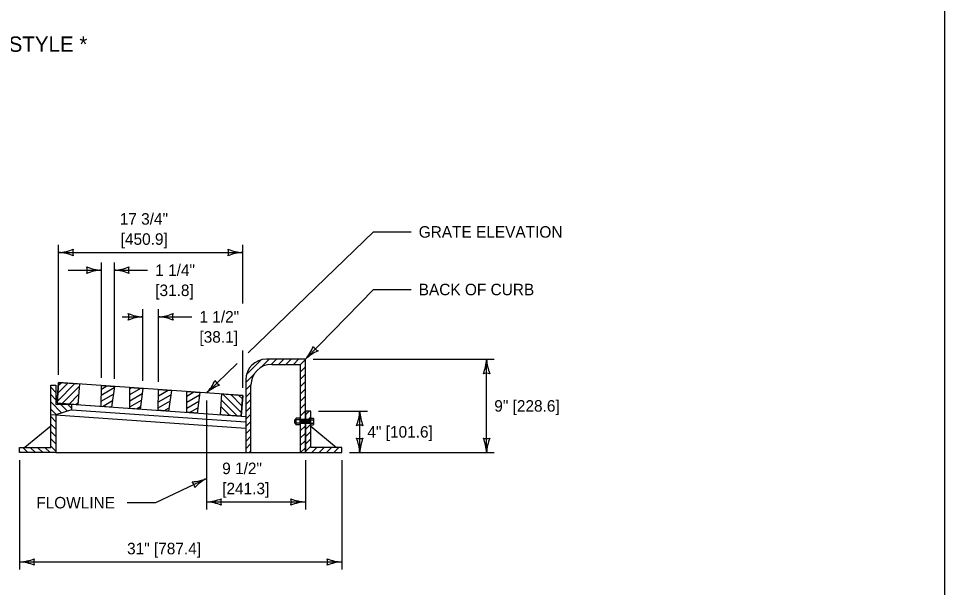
# Model space of a CAD drawing. Extents: x 49991.4 to 50057, y 49987.6 to 50011.4.
# Drawn here: x 50011.925 to 50016.75, y 49993.242 to 49996.209 of the extents above; entities that cross this region are included whole.
import ezdxf

# ---------------------------------------------------------------- set-up
doc = ezdxf.new("R2010")
doc.units = 0
for name, color, linetype in [('Level 1', 7, 'Continuous'), ('Level 2', 7, 'Continuous'), ('Level 3', 7, 'Continuous')]:
    doc.layers.add(name, color=color, linetype=linetype)

msp = doc.modelspace()

# ---------------------------------------------------------------- linework, layer by layer
at = {"layer": 'Level 1'}
for p, q in [((50013.113, 49994.3523), (50013.1892, 49994.4285)), ((50013.1885, 49994.3896), (50013.2313, 49994.4323)), ((50013.2425, 49994.4052), (50013.2696, 49994.4323)), ((50013.2808, 49994.4052), (50013.3079, 49994.4323)), ((50013.3191, 49994.4052), (50013.3462, 49994.4323)), ((50013.3574, 49994.4052), (50013.3845, 49994.4323)), ((50013.3936, 49994.4031), (50013.4206, 49994.4302)), ((50013.3936, 49994.3648), (50013.4206, 49994.3919)), ((50012.1344, 49994.3104), (50012.1269, 49994.2024)), ((50013.0935, 49994.2434), (50012.1344, 49994.3104)), ((50013.1092, 49994.3102), (50013.1519, 49994.353)), ((50013.3936, 49994.3265), (50013.4206, 49994.3536)), ((50013.3936, 49994.2882), (50013.4206, 49994.3153)), ((50012.0936, 49994.2857), (50012.1206, 49994.2586)), ((50012.1277, 49994.2138), (50012.2184, 49994.3046)), ((50012.1305, 49994.255), (50012.1826, 49994.3071)), ((50012.1334, 49994.2961), (50012.1468, 49994.3096)), ((50012.1527, 49994.2005), (50012.2415, 49994.2894)), ((50012.3569, 49994.2453), (50012.424, 49994.2841)), ((50012.3572, 49994.2767), (50012.3852, 49994.2929)), ((50012.5056, 49994.2473), (50012.5631, 49994.2805)), ((50012.5059, 49994.2787), (50012.5148, 49994.2838)), ((50012.6543, 49994.2406), (50012.706, 49994.2705)), ((50012.6545, 49994.272), (50012.6577, 49994.2738)), ((50013.1092, 49994.2719), (50013.1363, 49994.299)), ((50013.3936, 49994.2499), (50013.4206, 49994.277)), ((50012.0936, 49994.2474), (50012.1206, 49994.2203)), ((50012.1885, 49994.198), (50012.2387, 49994.2482)), ((50012.3567, 49994.2139), (50012.4195, 49994.2502)), ((50012.3624, 49994.1859), (50012.415, 49994.2163)), ((50012.5052, 49994.1844), (50012.5654, 49994.2192)), ((50012.5054, 49994.2158), (50012.5699, 49994.2531)), ((50012.654, 49994.2092), (50012.719, 49994.2467)), ((50012.8027, 49994.2086), (50012.869, 49994.2469)), ((50012.8029, 49994.24), (50012.8395, 49994.2611)), ((50012.9832, 49994.2189), (50013.0654, 49994.1367)), ((50012.9898, 49994.2506), (50013.0872, 49994.1532)), ((50013.031, 49994.2477), (50013.0897, 49994.189)), ((50013.0722, 49994.2449), (50013.0922, 49994.2248)), ((50013.086, 49994.135), (50013.0935, 49994.2434)), ((50013.1092, 49994.2336), (50013.1363, 49994.2607)), ((50013.1092, 49994.1953), (50013.1363, 49994.2224)), ((50013.3936, 49994.2116), (50013.4206, 49994.2387)), ((50012.0936, 49994.2091), (50012.1513, 49994.1514)), ((50012.0936, 49994.1708), (50012.1226, 49994.1418)), ((50012.1269, 49994.2024), (50013.086, 49994.1353)), ((50012.1452, 49994.1958), (50012.18, 49994.161)), ((50012.1828, 49994.1965), (50012.2019, 49994.1774)), ((50012.2019, 49994.1968), (50012.2019, 49994.1968)), ((50012.2019, 49994.1968), (50013.1092, 49994.1333)), ((50012.2019, 49994.1683), (50013.1092, 49994.1048)), ((50012.2243, 49994.1955), (50012.2358, 49994.207)), ((50012.5403, 49994.1735), (50012.5609, 49994.1853)), ((50012.6538, 49994.1778), (50012.7145, 49994.2128)), ((50012.6832, 49994.1635), (50012.71, 49994.179)), ((50012.8025, 49994.1772), (50012.8645, 49994.213)), ((50012.8167, 49994.1541), (50012.86, 49994.1792)), ((50012.9807, 49994.1831), (50013.0243, 49994.1396)), ((50013.1092, 49994.157), (50013.1363, 49994.1841)), ((50013.3936, 49994.1733), (50013.4206, 49994.2004)), ((50012.0936, 49994.1431), (50013.1092, 49994.072)), ((50012.0936, 49994.1325), (50012.1206, 49994.1054)), ((50012.2679, 49994.1635), (50012.2679, 49994.1635)), ((50012.9782, 49994.1473), (50012.9831, 49994.1424)), ((50013.1092, 49994.1187), (50013.1363, 49994.1458)), ((50013.3628, 49994.1141), (50013.3661, 49994.1175)), ((50013.3661, 49994.1175), (50013.3661, 49994.0972)), ((50013.3695, 49994.1175), (50013.3661, 49994.1175)), ((50013.3695, 49994.0941), (50013.3695, 49994.1205)), ((50013.3695, 49994.1175), (50013.3695, 49994.0972)), ((50013.3927, 49994.1249), (50013.3718, 49994.1249)), ((50013.3927, 49994.0897), (50013.3927, 49994.1249)), ((50013.3936, 49994.1225), (50013.3927, 49994.1225)), ((50013.3936, 49994.135), (50013.4206, 49994.1621)), ((50013.3936, 49994.0967), (50013.4206, 49994.1238)), ((50013.3936, 49994.0921), (50013.3936, 49994.1225)), ((50013.4477, 49994.1175), (50013.3936, 49994.1175)), ((50013.3966, 49994.1175), (50013.3966, 49994.0972)), ((50013.4, 49994.1175), (50013.4, 49994.0972)), ((50013.4033, 49994.1175), (50013.4033, 49994.0972)), ((50013.4067, 49994.1175), (50013.4067, 49994.0972)), ((50013.4101, 49994.1175), (50013.4101, 49994.0972)), ((50013.4135, 49994.1175), (50013.4135, 49994.0972)), ((50013.4169, 49994.1175), (50013.4169, 49994.0972)), ((50013.4203, 49994.1175), (50013.4203, 49994.0972)), ((50013.4206, 49994.1422), (50013.4399, 49994.1615)), ((50013.4206, 49994.1039), (50013.4477, 49994.131)), ((50013.4237, 49994.1175), (50013.4237, 49994.0972)), ((50013.427, 49994.1175), (50013.427, 49994.0972)), ((50013.4304, 49994.1175), (50013.4304, 49994.0972)), ((50013.4338, 49994.1175), (50013.4338, 49994.0972)), ((50013.4372, 49994.1175), (50013.4372, 49994.0972)), ((50013.4406, 49994.1175), (50013.4406, 49994.0972)), ((50013.444, 49994.1175), (50013.444, 49994.0972)), ((50013.4477, 49994.0921), (50013.4477, 49994.1225)), ((50013.4477, 49994.1225), (50013.4486, 49994.1225)), ((50013.4486, 49994.1249), (50013.4613, 49994.1249)), ((50013.4486, 49994.0897), (50013.4486, 49994.1249)), ((50013.4637, 49994.0941), (50013.4637, 49994.1205)), ((50012.0936, 49994.083), (50011.9581, 49993.9719)), ((50012.0936, 49994.0942), (50012.1206, 49994.0671)), ((50013.1092, 49994.0804), (50013.1363, 49994.1075)), ((50013.1092, 49994.0421), (50013.1363, 49994.0692)), ((50013.3627, 49994.1141), (50013.3627, 49994.1005)), ((50013.3628, 49994.1005), (50013.3661, 49994.0972)), ((50013.3644, 49994.1141), (50013.3644, 49994.1005)), ((50013.3695, 49994.0972), (50013.3661, 49994.0972)), ((50013.3678, 49994.1141), (50013.3678, 49994.1005)), ((50013.3927, 49994.1161), (50013.3718, 49994.1161)), ((50013.3927, 49994.0985), (50013.3718, 49994.0985)), ((50013.3927, 49994.0897), (50013.3718, 49994.0897)), ((50013.3936, 49994.0921), (50013.3927, 49994.0921)), ((50013.4477, 49994.0972), (50013.3936, 49994.0972)), ((50013.3936, 49994.0584), (50013.4206, 49994.0855)), ((50013.3949, 49994.1141), (50013.3949, 49994.1005)), ((50013.3983, 49994.1141), (50013.3983, 49994.1005)), ((50013.4017, 49994.1141), (50013.4017, 49994.1005)), ((50013.405, 49994.1141), (50013.405, 49994.1005)), ((50013.4084, 49994.1141), (50013.4084, 49994.1005)), ((50013.4118, 49994.1141), (50013.4118, 49994.1005)), ((50013.4152, 49994.1141), (50013.4152, 49994.1005)), ((50013.4186, 49994.1141), (50013.4186, 49994.1005)), ((50013.4206, 49994.0656), (50013.4477, 49994.0927)), ((50013.422, 49994.1141), (50013.422, 49994.1005)), ((50013.4254, 49994.1141), (50013.4254, 49994.1005)), ((50013.4287, 49994.1141), (50013.4287, 49994.1005)), ((50013.4321, 49994.1141), (50013.4321, 49994.1005)), ((50013.4355, 49994.1141), (50013.4355, 49994.1005)), ((50013.4389, 49994.1141), (50013.4389, 49994.1005)), ((50013.4423, 49994.1141), (50013.4423, 49994.1005)), ((50013.4457, 49994.1141), (50013.4457, 49994.1005)), ((50013.4477, 49994.0921), (50013.4486, 49994.0921)), ((50013.4477, 49994.083), (50013.4477, 49994.083)), ((50013.4477, 49994.083), (50013.5831, 49993.9719)), ((50013.4486, 49994.1161), (50013.4613, 49994.1161)), ((50013.4486, 49994.0985), (50013.4613, 49994.0985)), ((50013.4486, 49994.0897), (50013.4613, 49994.0897)), ((50012.0936, 49994.0559), (50012.1206, 49994.0288)), ((50013.1092, 49994.0038), (50013.1363, 49994.0309)), ((50013.3936, 49994.0201), (50013.4206, 49994.0472)), ((50013.4206, 49994.0273), (50013.4477, 49994.0544)), ((50012.0936, 49994.0176), (50012.1206, 49993.9905)), ((50012.0936, 49993.9793), (50012.1206, 49993.9522)), ((50013.1092, 49993.9655), (50013.1363, 49993.9926)), ((50013.3936, 49993.9818), (50013.4206, 49994.0089)), ((50013.4206, 49993.989), (50013.4477, 49994.0161)), ((50013.4206, 49993.9507), (50013.4477, 49993.9778)), ((50011.9311, 49993.9503), (50011.9365, 49993.9448)), ((50011.9311, 49993.9503), (50011.9365, 49993.9448)), ((50011.9311, 49993.9448), (50011.9311, 49993.9448)), ((50011.9477, 49993.9719), (50011.9748, 49993.9448)), ((50011.9581, 49993.9719), (50011.9581, 49993.9719)), ((50011.986, 49993.9719), (50012.0131, 49993.9448)), ((50012.0244, 49993.9719), (50012.0514, 49993.9448)), ((50012.0627, 49993.9719), (50012.0897, 49993.9448)), ((50012.1206, 49993.9448), (50013.4206, 49993.9448)), ((50013.1268, 49993.9448), (50013.1363, 49993.9543)), ((50013.3949, 49993.9448), (50013.4206, 49993.9706)), ((50013.4531, 49993.9448), (50013.4801, 49993.9719)), ((50013.4914, 49993.9448), (50013.5184, 49993.9719)), ((50013.5297, 49993.9448), (50013.5567, 49993.9719)), ((50013.568, 49993.9448), (50013.595, 49993.9719)), ((50013.5831, 49993.9719), (50013.5831, 49993.9719)), ((50013.6063, 49993.9448), (50013.6102, 49993.9488))]:
    msp.add_line(p, q, dxfattribs=at)
for points in [[(49999.3835, 49998.9992), (50016.7501, 49998.9992), (50016.7501, 49987.7988), (49999.3835, 49987.7988)], [(50012.1344, 49994.3104), (50012.2425, 49994.3029), (50012.2349, 49994.1947), (50012.1269, 49994.2023)], [(50012.1206, 49994.1412), (50012.1206, 49993.9448), (50011.9311, 49993.9448), (50011.9311, 49993.9719), (50012.0936, 49993.9719), (50012.0936, 49994.2969), (50012.1206, 49994.2969), (50012.1206, 49994.1953), (50012.2019, 49994.1968), (50012.2019, 49994.1683)], [(50012.3565, 49994.1863), (50012.3573, 49994.2948), (50012.4249, 49994.2901), (50012.4105, 49994.1825)], [(50012.5051, 49994.1759), (50012.5059, 49994.2845), (50012.5734, 49994.2797), (50012.5591, 49994.1721)], [(50012.5051, 49994.1759), (50012.5059, 49994.2845), (50012.5734, 49994.2797), (50012.5591, 49994.1721)], [(50012.6537, 49994.1655), (50012.6545, 49994.2741), (50012.722, 49994.2693), (50012.7077, 49994.1617)], [(50012.8023, 49994.1551), (50012.8031, 49994.2637), (50012.8706, 49994.259), (50012.8563, 49994.1514)], [(50012.8023, 49994.1551), (50012.8031, 49994.2637), (50012.8706, 49994.259), (50012.8563, 49994.1514)], [(50012.9855, 49994.2509), (50013.0935, 49994.2434), (50013.086, 49994.1352), (50012.9779, 49994.1428)], [(50013.4477, 49993.9719), (50013.4477, 49994.1615), (50013.4206, 49994.1615), (50013.4206, 49993.9448), (50013.6102, 49993.9448), (50013.6102, 49993.9719)]]:
    msp.add_lwpolyline(points, close=True, dxfattribs=at)
for points in [[(50013.4206, 49993.9448), (50013.4206, 49994.4323), (50013.2175, 49994.4323)], [(50013.2446, 49994.4052), (50013.3936, 49994.4052), (50013.3936, 49993.9448), (50013.4206, 49993.9448)], [(50013.1092, 49994.324), (50013.1092, 49993.9448), (50013.1363, 49993.9448), (50013.1363, 49994.2969)]]:
    msp.add_lwpolyline(points, dxfattribs=at)
for centre, radius, start, end in [((50013.2175, 49994.324), 0.1083, 90, 180), ((50013.2446, 49994.2969), 0.1083, 90, 180), ((50013.3748, 49994.1205), 0.00528, 123.6844, 236.3156), ((50013.4584, 49994.1205), 0.00528, 303.6844, 56.3156), ((50013.3871, 49994.1073), 0.0176, 150.0207, 209.9793), ((50013.3748, 49994.0941), 0.00528, 123.6376, 236.3624), ((50013.4461, 49994.1073), 0.0176, 330.0207, 29.9793), ((50013.4584, 49994.0941), 0.00528, 303.6376, 56.3624)]:
    msp.add_arc(centre, radius, start, end, dxfattribs=at)
at = {"layer": 'Level 3'}
for p, q in [((50013.1223, 49994.4652), (50013.7756, 49995.0958)), ((50013.7756, 49995.0958), (50013.9706, 49995.0958)), ((50012.1344, 49994.3504), (50012.1344, 49995.0286)), ((50012.1344, 49994.9886), (50013.0935, 49994.9886)), ((50013.0935, 49994.7232), (50013.0935, 49995.0286)), ((50012.1839, 49994.8963), (50012.3573, 49994.8963)), ((50012.3573, 49994.3348), (50012.3573, 49994.9363)), ((50012.4249, 49994.3301), (50012.4249, 49994.9363)), ((50012.4249, 49994.8963), (50012.5983, 49994.8963)), ((50013.7756, 49994.7955), (50013.4206, 49994.4323)), ((50013.7756, 49994.7955), (50013.9706, 49994.7955)), ((50012.4649, 49994.6532), (50012.5734, 49994.6532)), ((50012.5734, 49994.3197), (50012.5734, 49994.6932)), ((50012.6545, 49994.3141), (50012.6545, 49994.6932)), ((50012.6545, 49994.6532), (50012.8279, 49994.6532)), ((50013.0935, 49994.2834), (50013.0935, 49994.4782)), ((50012.9061, 49994.2565), (50013.0648, 49994.4097)), ((50013.4606, 49994.4323), (50014.4044, 49994.4323)), ((50014.3644, 49993.9448), (50014.3644, 49994.4323)), ((50012.9061, 49993.6478), (50012.9061, 49994.2165)), ((50013.4877, 49994.1615), (50013.7433, 49994.1615)), ((50013.7033, 49993.9448), (50013.7033, 49994.1615)), ((50013.6502, 49993.9448), (50014.4044, 49993.9448)), ((50011.9311, 49993.9048), (50011.9311, 49993.3348)), ((50013.4206, 49993.9048), (50013.4206, 49993.6478)), ((50013.6102, 49993.9048), (50013.6102, 49993.3348)), ((50012.9061, 49993.8107), (50012.6399, 49993.6839)), ((50012.6399, 49993.6839), (50012.4911, 49993.6839)), ((50012.9061, 49993.6878), (50013.4206, 49993.6878)), ((50011.9311, 49993.3748), (50013.6102, 49993.3748))]:
    msp.add_line(p, q, dxfattribs=at)
for centre, radius, start, end in [((50012.1229, 49995.2213), 0.233, 272.8273, 292.0772), ((50012.1253, 49994.7665), 0.2223, 67.456, 87.6395), ((50012.2626, 49994.9886), 0.0548, 162.1388, 197.8612), ((50013.1027, 49995.2107), 0.2223, 247.456, 267.6395), ((50012.9653, 49994.9886), 0.0548, 342.1388, 17.8612), ((50013.105, 49994.7559), 0.233, 92.8273, 112.0772), ((50012.3665, 49995.1184), 0.2223, 247.456, 267.6395), ((50012.2291, 49994.8963), 0.0548, 342.1388, 17.8612), ((50012.3688, 49994.6636), 0.233, 92.8273, 112.0772), ((50012.4134, 49995.129), 0.233, 272.8273, 292.0772), ((50012.4157, 49994.6742), 0.2223, 67.456, 87.6395), ((50012.5531, 49994.8963), 0.0548, 162.1388, 197.8612), ((50012.5826, 49994.8753), 0.2223, 247.456, 267.6395), ((50012.4452, 49994.6532), 0.0548, 342.1388, 17.8612), ((50012.5849, 49994.4205), 0.233, 92.8273, 112.0772), ((50012.643, 49994.8859), 0.233, 272.8273, 292.0772), ((50012.6453, 49994.431), 0.2223, 67.456, 87.6395), ((50012.7827, 49994.6532), 0.0548, 162.1388, 197.8612), ((50013.2462, 49994.5868), 0.233, 318.4827, 337.7326), ((50013.5731, 49994.2705), 0.2223, 113.1114, 133.2949), ((50013.5103, 49994.524), 0.0548, 207.7942, 243.5166), ((50014.1422, 49994.4415), 0.2223, 337.456, 357.6395), ((50014.5971, 49994.4438), 0.233, 182.8273, 202.0772), ((50014.3644, 49994.3041), 0.0548, 72.1388, 107.8612), ((50012.7362, 49994.4159), 0.233, 316.8137, 336.0635), ((50012.9983, 49994.3455), 0.0548, 206.1252, 241.8475), ((50013.0537, 49994.0903), 0.2223, 111.4424, 131.6259), ((50013.4812, 49994.1706), 0.2223, 337.456, 357.6395), ((50013.936, 49994.173), 0.233, 182.8273, 202.0772), ((50013.7033, 49994.0333), 0.0548, 72.1388, 107.8612), ((50013.7033, 49994.073), 0.0548, 252.1388, 287.8612), ((50013.4706, 49993.9333), 0.233, 2.8273, 22.0772), ((50013.9255, 49993.9357), 0.2223, 157.456, 177.6395), ((50014.3644, 49994.073), 0.0548, 252.1388, 287.8612), ((50014.1316, 49993.9333), 0.233, 2.8273, 22.0772), ((50014.5865, 49993.9357), 0.2223, 157.456, 177.6395), ((50012.8189, 49994.0152), 0.2223, 272.9102, 293.0937), ((50012.7903, 49993.7555), 0.0548, 7.593, 43.3154), ((50013.0165, 49993.6055), 0.233, 118.2815, 137.5314), ((50012.8946, 49993.9205), 0.233, 272.8273, 292.0772), ((50012.8969, 49993.4656), 0.2223, 67.456, 87.6395), ((50013.0343, 49993.6878), 0.0548, 162.1388, 197.8612), ((50013.4298, 49993.9099), 0.2223, 247.456, 267.6395), ((50013.2924, 49993.6878), 0.0548, 342.1388, 17.8612), ((50013.4321, 49993.455), 0.233, 92.8273, 112.0772), ((50011.9196, 49993.6075), 0.233, 272.8273, 292.0772), ((50011.9219, 49993.1527), 0.2223, 67.456, 87.6395), ((50012.0593, 49993.3748), 0.0548, 162.1388, 197.8612), ((50013.6194, 49993.5969), 0.2223, 247.456, 267.6395), ((50013.482, 49993.3748), 0.0548, 342.1388, 17.8612), ((50013.6217, 49993.1421), 0.233, 92.8273, 112.0772)]:
    msp.add_arc(centre, radius, start, end, dxfattribs=at)

# ---------------------------------------------------------------- texts
at = {"layer": 'Level 2'}
for s, height, p in [('CURVED VANE STYLE *', 0.08, (50011.0714, 49996.0349)), ('17 3/4"', 0.06, (50012.4528, 49995.1336)), ('[450.9]', 0.06, (50012.4578, 49995.0286)), ('GRATE ELEVATION ', 0.06, (50014.0106, 49995.0658)), ('1 1/4"', 0.06, (50012.6377, 49994.8663)), ('[31.8]', 0.06, (50012.6377, 49994.7613)), ('BACK OF CURB', 0.06, (50014.0106, 49994.7655)), ('1 1/2"', 0.06, (50012.868, 49994.6232)), ('[38.1]', 0.06, (50012.868, 49994.5182)), ('9" [228.6]', 0.06, (50014.4044, 49994.1586)), ('4" [101.6]', 0.06, (50013.7433, 49994.0232)), ('9 1/2"', 0.06, (50012.9867, 49993.8328)), ('[241.3]', 0.06, (50012.9867, 49993.7278)), ('FLOWLINE', 0.06, (50012.0179, 49993.6539)), ('31" [787.4]', 0.06, (50012.491, 49993.4148))]:
    msp.add_text(s, height=height, dxfattribs=at).set_placement(p)

doc.saveas('drawing.dxf')
